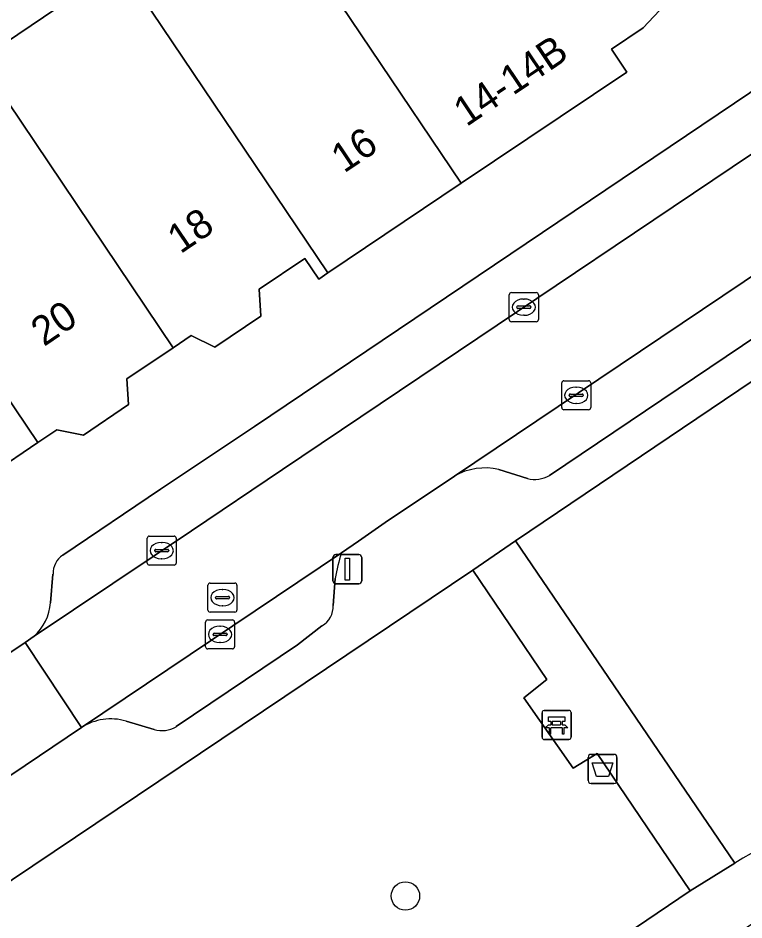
# Model space of a CAD drawing. Extents: x 159960 to 160866, y 382700 to 383354.
# Drawn here: x 160527.58 to 160552.56, y 382938.64 to 382969.69 of the extents above; entities that cross this region are included whole.
import ezdxf

# ---------------------------------------------------------------- set-up
doc = ezdxf.new("R2010")
doc.units = 0
for name, color, linetype in [('IMGEO_Afvalbak', 7, 'Continuous'), ('IMGEO_Bank', 7, 'Continuous'), ('IMGEO_Boom', 7, 'Continuous'), ('IMGEO_Erf', 7, 'Continuous'), ('IMGEO_Groenvoorziening', 7, 'Continuous'), ('IMGEO_Kolk', 7, 'Continuous'), ('IMGEO_Lichtmast', 7, 'Continuous'), ('IMGEO_Pand', 7, 'Continuous'), ('IMGEO_Pand_nummerreeks', 7, 'Continuous'), ('IMGEO_Parkeervlak_open', 7, 'Continuous'), ('IMGEO_Rijbaan_lokaal_gesloten', 7, 'Continuous'), ('IMGEO_Rijbaan_lokaal_open', 7, 'Continuous'), ('IMGEO_Rioolput', 7, 'Continuous'), ('IMGEO_Voetpad_open', 7, 'Continuous')]:
    doc.layers.add(name, color=color, linetype=linetype)

msp = doc.modelspace()

# ---------------------------------------------------------------- linework, layer by layer
at = {"layer": 'IMGEO_Afvalbak'}
for p, q in [((160547.296, 382944.34), (160548.086, 382944.34)), ((160548.086, 382944.34), (160547.296, 382944.34)), ((160547.196, 382943.44), (160547.196, 382944.24)), ((160547.196, 382944.24), (160547.196, 382943.44)), ((160548.186, 382944.24), (160548.186, 382943.44)), ((160548.186, 382943.44), (160548.186, 382944.24)), ((160548.086, 382943.34), (160547.296, 382943.34)), ((160547.296, 382943.34), (160548.086, 382943.34))]:
    msp.add_line(p, q, dxfattribs=at)
msp.add_lwpolyline([(160547.339, 382944.054), (160548.043, 382944.054), (160547.894, 382943.584), (160547.488, 382943.584), (160547.339, 382944.054)], dxfattribs=at)
for centre, start, end in [((160547.296, 382944.24), 90, 180), ((160547.296, 382944.24), 90, 180), ((160548.086, 382944.24), 0, 90), ((160548.086, 382944.24), 360, 90), ((160547.296, 382943.44), 180, 270), ((160547.296, 382943.44), 180, 270), ((160548.086, 382943.44), 270, 0), ((160548.086, 382943.44), 270, 0)]:
    msp.add_arc(centre, 0.1, start, end, dxfattribs=at)
at = {"layer": 'IMGEO_Bank'}
for p, q in [((160545.685, 382945.854), (160546.526, 382945.854)), ((160546.526, 382945.854), (160545.685, 382945.854)), ((160545.61, 382944.929), (160545.61, 382945.77)), ((160545.61, 382945.77), (160545.61, 382944.929)), ((160546.61, 382945.779), (160546.61, 382944.938)), ((160546.61, 382944.938), (160546.61, 382945.779)), ((160546.307, 382945.252), (160545.914, 382945.252)), ((160545.919, 382945.36), (160545.919, 382945.466)), ((160545.963, 382945.466), (160545.963, 382945.36)), ((160546.251, 382945.472), (160545.969, 382945.472)), ((160545.969, 382945.354), (160546.251, 382945.354)), ((160546.257, 382945.36), (160546.257, 382945.466)), ((160546.301, 382945.466), (160546.301, 382945.36)), ((160546.535, 382944.854), (160545.694, 382944.854)), ((160545.694, 382944.854), (160546.535, 382944.854))]:
    msp.add_line(p, q, dxfattribs=at)
for points in [[(160545.913, 382945.472), (160545.827, 382945.472), (160545.827, 382945.633), (160546.39, 382945.633), (160546.39, 382945.472), (160546.307, 382945.472)], [(160545.857, 382945.252), (160545.715, 382945.252), (160545.827, 382945.354), (160545.913, 382945.354)], [(160545.907, 382945.245), (160545.907, 382945.038), (160545.864, 382945.038), (160545.864, 382945.245)], [(160546.307, 382945.354), (160546.39, 382945.354), (160546.502, 382945.252), (160546.363, 382945.252)], [(160546.357, 382945.245), (160546.357, 382945.038), (160546.313, 382945.038), (160546.313, 382945.245)]]:
    msp.add_lwpolyline(points, dxfattribs=at)
for centre, radius, start, end in [((160545.688, 382945.776), 0.0779, 92.4484, 184.2845), ((160545.688, 382945.776), 0.0779, 92.4484, 184.2845), ((160546.532, 382945.776), 0.0779, 2.4484, 94.2845), ((160546.532, 382945.776), 0.0779, 2.4484, 94.2845), ((160545.857, 382945.245), 0.00671, 2.8957, 87.1043), ((160545.914, 382945.245), 0.00671, 92.8957, 177.1043), ((160545.912, 382945.465), 0.00671, 2.8957, 87.1043), ((160545.912, 382945.361), 0.00671, 272.8957, 357.1043), ((160545.969, 382945.465), 0.00671, 92.8957, 177.1043), ((160545.969, 382945.361), 0.00671, 182.8957, 267.1043), ((160546.251, 382945.465), 0.00671, 2.8957, 87.1043), ((160546.251, 382945.361), 0.00671, 272.8957, 357.1043), ((160546.308, 382945.465), 0.00671, 92.8957, 177.1043), ((160546.308, 382945.361), 0.00671, 182.8957, 267.1043), ((160546.306, 382945.245), 0.00671, 2.8957, 87.1043), ((160546.363, 382945.245), 0.00671, 92.8957, 177.1043), ((160545.688, 382944.932), 0.0779, 182.4484, 274.2845), ((160545.688, 382944.932), 0.0779, 182.4484, 274.2845), ((160546.532, 382944.932), 0.0779, 272.4484, 4.2845), ((160546.532, 382944.932), 0.0779, 272.4484, 4.2845)]:
    msp.add_arc(centre, radius, start, end, dxfattribs=at)
at = {"layer": 'IMGEO_Boom'}
msp.add_circle((160540.911, 382939.468), 0.489, dxfattribs=at)
at = {"layer": 'IMGEO_Erf'}
msp.add_lwpolyline([(160502.775, 382952.364), (160507.464, 382955.534), (160512.198, 382958.735), (160516.845, 382961.877), (160521.541, 382965.052), (160526.252, 382968.237), (160531.102, 382971.516)], dxfattribs=at)
at = {"layer": 'IMGEO_Groenvoorziening'}
for points in [[(160564.76, 382965.194), (160563.415, 382964.323), (160544.698, 382951.695), (160552.24, 382940.596)], [(160543.966, 382935.075), (160550.712, 382939.643), (160547.503, 382944.374), (160546.683, 382943.866), (160544.984, 382946.283), (160545.775, 382946.922), (160543.226, 382950.68), (160500, 382921.626), (160496.721, 382919.422), (160500, 382914.514), (160503.626, 382909.085), (160504.654, 382907.546), (160527.954, 382923.207)]]:
    msp.add_lwpolyline(points, dxfattribs=at)
msp.add_arc((160569.366, 382912.423), 32.97, 103.0217, 121.2945, dxfattribs=at)
at = {"layer": 'IMGEO_Kolk'}
for p, q in [((160544.483, 382959.31), (160544.483, 382960.162)), ((160544.558, 382960.236), (160545.41, 382960.236)), ((160545.484, 382960.162), (160545.484, 382959.31)), ((160544.971, 382960.016), (160544.996, 382960.016)), ((160544.742, 382959.73), (160544.742, 382959.742)), ((160545.18, 382959.693), (160544.782, 382959.693)), ((160544.785, 382959.779), (160545.183, 382959.779)), ((160545.226, 382959.742), (160545.226, 382959.73)), ((160545.41, 382959.236), (160544.558, 382959.236)), ((160544.994, 382959.456), (160544.969, 382959.456)), ((160546.287, 382956.277), (160546.287, 382957.129)), ((160546.362, 382957.203), (160547.214, 382957.203)), ((160547.288, 382957.129), (160547.288, 382956.277)), ((160546.589, 382956.746), (160546.987, 382956.746)), ((160546.775, 382956.983), (160546.8, 382956.983)), ((160546.546, 382956.697), (160546.546, 382956.709)), ((160546.984, 382956.66), (160546.586, 382956.66)), ((160546.798, 382956.423), (160546.773, 382956.423)), ((160547.03, 382956.709), (160547.03, 382956.697)), ((160547.214, 382956.203), (160546.362, 382956.203)), ((160532.024, 382950.929), (160532.024, 382951.781)), ((160532.099, 382951.855), (160532.951, 382951.855)), ((160533.025, 382951.781), (160533.025, 382950.929)), ((160532.512, 382951.635), (160532.537, 382951.635)), ((160532.283, 382951.349), (160532.283, 382951.361)), ((160532.721, 382951.312), (160532.323, 382951.312)), ((160532.326, 382951.398), (160532.724, 382951.398)), ((160532.767, 382951.361), (160532.767, 382951.349)), ((160532.951, 382950.855), (160532.099, 382950.855)), ((160532.535, 382951.075), (160532.51, 382951.075)), ((160534.108, 382948.972), (160534.96, 382948.972)), ((160534.033, 382948.046), (160534.033, 382948.898)), ((160534.521, 382948.752), (160534.546, 382948.752)), ((160535.034, 382948.898), (160535.034, 382948.046)), ((160534.292, 382948.466), (160534.292, 382948.478)), ((160534.73, 382948.429), (160534.332, 382948.429)), ((160534.335, 382948.515), (160534.733, 382948.515)), ((160534.776, 382948.478), (160534.776, 382948.466)), ((160534.544, 382948.192), (160534.519, 382948.192)), ((160534.96, 382947.972), (160534.108, 382947.972))]:
    msp.add_line(p, q, dxfattribs=at)
for points in [[(160544.483, 382959.31), (160544.483, 382960.162)], [(160544.558, 382960.236), (160545.41, 382960.236)], [(160545.484, 382960.162), (160545.484, 382959.31)], [(160545.41, 382959.236), (160544.558, 382959.236)], [(160546.287, 382956.277), (160546.287, 382957.129)], [(160546.362, 382957.203), (160547.214, 382957.203)], [(160547.288, 382957.129), (160547.288, 382956.277)], [(160547.214, 382956.203), (160546.362, 382956.203)], [(160532.024, 382950.929), (160532.024, 382951.781)], [(160532.099, 382951.855), (160532.951, 382951.855)], [(160533.025, 382951.781), (160533.025, 382950.929)], [(160532.951, 382950.855), (160532.099, 382950.855)], [(160534.108, 382948.972), (160534.96, 382948.972)], [(160534.033, 382948.046), (160534.033, 382948.898)], [(160535.034, 382948.898), (160535.034, 382948.046)], [(160534.96, 382947.972), (160534.108, 382947.972)]]:
    msp.add_lwpolyline(points, dxfattribs=at)
for centre, radius, start, end in [((160544.56, 382960.16), 0.0765, 91.552, 178.448), ((160544.56, 382960.16), 0.0765, 91.552, 178.448), ((160545.408, 382960.16), 0.0765, 1.552, 88.448), ((160545.408, 382960.16), 0.0765, 1.552, 88.448), ((160544.782, 382959.739), 0.0403, 85.8775, 175.7526), ((160544.779, 382959.729), 0.0366, 178.938, 274.7102), ((160545.183, 382959.736), 0.043, 264.8664, 352.4533), ((160545.187, 382959.741), 0.0386, 1.7309, 96.639), ((160544.56, 382959.312), 0.0765, 181.552, 268.448), ((160544.56, 382959.312), 0.0765, 181.552, 268.448), ((160545.408, 382959.312), 0.0765, 271.552, 358.448), ((160545.408, 382959.312), 0.0765, 271.552, 358.448), ((160546.364, 382957.127), 0.0765, 91.552, 178.448), ((160546.364, 382957.127), 0.0765, 91.552, 178.448), ((160547.212, 382957.127), 0.0765, 1.552, 88.448), ((160547.212, 382957.127), 0.0765, 1.552, 88.448), ((160546.586, 382956.706), 0.0403, 85.8775, 175.7526), ((160546.991, 382956.708), 0.0386, 1.7309, 96.639), ((160546.583, 382956.696), 0.0366, 178.938, 274.7102), ((160546.987, 382956.703), 0.043, 264.8664, 352.4533), ((160546.364, 382956.279), 0.0765, 181.552, 268.448), ((160546.364, 382956.279), 0.0765, 181.552, 268.448), ((160547.212, 382956.279), 0.0765, 271.552, 358.448), ((160547.212, 382956.279), 0.0765, 271.552, 358.448), ((160532.101, 382951.779), 0.0765, 91.552, 178.448), ((160532.101, 382951.779), 0.0765, 91.552, 178.448), ((160532.949, 382951.779), 0.0765, 1.552, 88.448), ((160532.949, 382951.779), 0.0765, 1.552, 88.448), ((160532.323, 382951.358), 0.0403, 85.8775, 175.7526), ((160532.32, 382951.348), 0.0366, 178.938, 274.7102), ((160532.724, 382951.355), 0.043, 264.8664, 352.4533), ((160532.728, 382951.36), 0.0386, 1.7309, 96.639), ((160532.101, 382950.931), 0.0765, 181.552, 268.448), ((160532.101, 382950.931), 0.0765, 181.552, 268.448), ((160532.949, 382950.931), 0.0765, 271.552, 358.448), ((160532.949, 382950.931), 0.0765, 271.552, 358.448), ((160534.11, 382948.896), 0.0765, 91.552, 178.448), ((160534.11, 382948.896), 0.0765, 91.552, 178.448), ((160534.958, 382948.896), 0.0765, 1.552, 88.448), ((160534.958, 382948.896), 0.0765, 1.552, 88.448), ((160534.332, 382948.475), 0.0403, 85.8775, 175.7526), ((160534.329, 382948.465), 0.0366, 178.938, 274.7102), ((160534.733, 382948.472), 0.043, 264.8664, 352.4533), ((160534.737, 382948.477), 0.0386, 1.7309, 96.639), ((160534.11, 382948.048), 0.0765, 181.552, 268.448), ((160534.11, 382948.048), 0.0765, 181.552, 268.448), ((160534.958, 382948.048), 0.0765, 271.552, 358.448), ((160534.958, 382948.048), 0.0765, 271.552, 358.448)]:
    msp.add_arc(centre, radius, start, end, dxfattribs=at)
for centre, major_axis, ratio, start_param, end_param in [((160544.97, 382959.736), (-0.387, 0.002), 0.722429, 4.712389, 7.853982), ((160544.995, 382959.736), (-0.39, 0.002), 0.717154, 1.570796, 4.712389), ((160546.774, 382956.703), (-0.387, 0.002), 0.722429, 4.712389, 7.853982), ((160546.799, 382956.703), (-0.39, 0.002), 0.717154, 1.570796, 4.712389), ((160532.511, 382951.355), (-0.387, 0.002), 0.722429, 4.712389, 7.853982), ((160532.536, 382951.355), (-0.39, 0.002), 0.717154, 1.570796, 4.712389), ((160534.52, 382948.472), (-0.387, 0.002), 0.722429, 4.712389, 7.853982), ((160534.545, 382948.472), (-0.39, 0.002), 0.717154, 1.570796, 4.712389)]:
    msp.add_ellipse(centre, major_axis=major_axis, ratio=ratio, start_param=start_param, end_param=end_param, dxfattribs=at)
at = {"layer": 'IMGEO_Lichtmast'}
for p, q in [((160538.518, 382951.217), (160539.308, 382951.217)), ((160539.308, 382951.217), (160538.518, 382951.217)), ((160538.418, 382950.317), (160538.418, 382951.117)), ((160538.418, 382951.117), (160538.418, 382950.317)), ((160539.408, 382951.117), (160539.408, 382950.317)), ((160539.408, 382950.317), (160539.408, 382951.117)), ((160539.308, 382950.217), (160538.518, 382950.217)), ((160538.518, 382950.217), (160539.308, 382950.217))]:
    msp.add_line(p, q, dxfattribs=at)
msp.add_lwpolyline([(160538.838, 382951.092), (160538.988, 382951.092), (160538.988, 382950.342), (160538.838, 382950.342), (160538.838, 382951.092)], dxfattribs=at)
for centre, start, end in [((160538.518, 382951.117), 90, 180), ((160538.518, 382951.117), 90, 180), ((160539.308, 382951.117), 0, 90), ((160539.308, 382951.117), 360, 90), ((160538.518, 382950.317), 180, 270), ((160538.518, 382950.317), 180, 270), ((160539.308, 382950.317), 270, 0), ((160539.308, 382950.317), 270, 0)]:
    msp.add_arc(centre, 0.1, start, end, dxfattribs=at)
at = {"layer": 'IMGEO_Pand'}
for points in [[(160542.248, 382976.778), (160539.98, 382978.761), (160536.898, 382976.678), (160538.403, 382974.45), (160536.607, 382973.237), (160542.83, 382964.001), (160548.525, 382967.83), (160547.997, 382968.615), (160549.091, 382969.35), (160549.833, 382970.148)], [(160536.607, 382973.237), (160535.68, 382974.612), (160531.102, 382971.516), (160538.244, 382960.918), (160542.83, 382964.001)], [(160526.252, 382968.237), (160532.921, 382958.341), (160533.536, 382958.755), (160534.353, 382958.354), (160535.941, 382959.422), (160535.878, 382960.35), (160537.452, 382961.408), (160537.926, 382960.704), (160538.244, 382960.918), (160531.102, 382971.516)], [(160526.252, 382968.237), (160521.541, 382965.052), (160528.264, 382955.075), (160528.916, 382955.514), (160529.83, 382955.335), (160531.388, 382956.382), (160531.327, 382957.27), (160532.921, 382958.341)], [(160516.845, 382961.877), (160523.564, 382951.907), (160524.289, 382952.394), (160525.006, 382952.043), (160526.753, 382953.218), (160526.698, 382954.023), (160528.264, 382955.075), (160521.541, 382965.052)]]:
    msp.add_lwpolyline(points, close=True, dxfattribs=at)
at = {"layer": 'IMGEO_Parkeervlak_open'}
for points in [[(160528.138, 382948.406), (160533.549, 382952.042), (160536.679, 382954.15), (160558.21, 382968.628)], [(160554.974, 382968.604), (160535.715, 382955.631), (160532.484, 382953.473), (160529.119, 382951.203)], [(160555.401, 382962.522), (160542.597, 382953.924)], [(160545.868, 382953.947), (160554.155, 382959.529)], [(160544.124, 382954.151), (160545.109, 382953.839)], [(160538.708, 382951.282), (160529.769, 382945.267)], [(160528.785, 382950.548), (160528.702, 382949.556)], [(160538.429, 382949.469), (160538.491, 382950.396)], [(160537.2, 382948.111), (160538.035, 382948.767)], [(160533.023, 382945.296), (160537.2, 382948.111)], [(160531.299, 382945.487), (160532.26, 382945.2)]]:
    msp.add_lwpolyline(points, dxfattribs=at)
for centre, radius, start, end in [((160543.659, 382952.032), 2.169, 77.6097, 119.3013), ((160545.357, 382954.816), 1.008, 255.7469, 300.4499), ((160529.556, 382950.567), 0.771, 124.5158, 181.448), ((160545.811, 382949.073), 7.439, 162.7227, 169.7533), ((160526.944, 382949.705), 1.765, 312.5971, 355.153), ((160537.636, 382949.453), 0.793, 300.209, 1.1841), ((160530.774, 382943.708), 1.855, 73.5538, 122.8113), ((160532.534, 382946.105), 0.946, 253.1862, 301.1563)]:
    msp.add_arc(centre, radius, start, end, dxfattribs=at)
at = {"layer": 'IMGEO_Rijbaan_lokaal_gesloten'}
msp.add_arc((160569.011, 382913.206), 30.019, 101.6999, 123.2365, dxfattribs=at)
at = {"layer": 'IMGEO_Rijbaan_lokaal_open'}
for points in [[(160555.401, 382962.522), (160561.566, 382966.661), (160559.548, 382969.562), (160558.21, 382968.628), (160536.679, 382954.15), (160533.549, 382952.042), (160528.138, 382948.406), (160527.829, 382948.198), (160529.769, 382945.267), (160538.708, 382951.282), (160539.297, 382951.678), (160540.214, 382952.323), (160542.597, 382953.924)], [(160529.769, 382945.267), (160527.829, 382948.198), (160525.372, 382946.547), (160527.336, 382943.63)]]:
    msp.add_lwpolyline(points, close=True, dxfattribs=at)
at = {"layer": 'IMGEO_Rioolput'}
for p, q in [((160534.189, 382950.237), (160535.041, 382950.237)), ((160534.114, 382949.311), (160534.114, 382950.163)), ((160534.602, 382950.017), (160534.627, 382950.017)), ((160535.115, 382950.163), (160535.115, 382949.311)), ((160534.373, 382949.731), (160534.373, 382949.743)), ((160534.811, 382949.694), (160534.413, 382949.694)), ((160534.416, 382949.78), (160534.814, 382949.78)), ((160534.857, 382949.743), (160534.857, 382949.731)), ((160534.625, 382949.457), (160534.6, 382949.457)), ((160535.041, 382949.237), (160534.189, 382949.237))]:
    msp.add_line(p, q, dxfattribs=at)
for points in [[(160534.189, 382950.237), (160535.041, 382950.237)], [(160534.114, 382949.311), (160534.114, 382950.163)], [(160535.115, 382950.163), (160535.115, 382949.311)], [(160535.041, 382949.237), (160534.189, 382949.237)]]:
    msp.add_lwpolyline(points, dxfattribs=at)
for centre, radius, start, end in [((160534.191, 382950.161), 0.0765, 91.552, 178.448), ((160534.191, 382950.161), 0.0765, 91.552, 178.448), ((160535.039, 382950.161), 0.0765, 1.552, 88.448), ((160535.039, 382950.161), 0.0765, 1.552, 88.448), ((160534.413, 382949.74), 0.0403, 85.8775, 175.7526), ((160534.41, 382949.73), 0.0366, 178.938, 274.7102), ((160534.814, 382949.737), 0.043, 264.8664, 352.4533), ((160534.818, 382949.742), 0.0386, 1.7309, 96.639), ((160534.191, 382949.313), 0.0765, 181.552, 268.448), ((160534.191, 382949.313), 0.0765, 181.552, 268.448), ((160535.039, 382949.313), 0.0765, 271.552, 358.448), ((160535.039, 382949.313), 0.0765, 271.552, 358.448)]:
    msp.add_arc(centre, radius, start, end, dxfattribs=at)
for centre, major_axis, ratio, start_param, end_param in [((160534.601, 382949.737), (-0.387, 0.002), 0.722429, 4.712389, 7.853982), ((160534.626, 382949.737), (-0.39, 0.002), 0.717154, 1.570796, 4.712389)]:
    msp.add_ellipse(centre, major_axis=major_axis, ratio=ratio, start_param=start_param, end_param=end_param, dxfattribs=at)
at = {"layer": 'IMGEO_Voetpad_open'}
for points in [[(160549.833, 382970.148), (160549.091, 382969.35), (160547.997, 382968.615), (160548.525, 382967.83), (160542.83, 382964.001), (160538.244, 382960.918), (160537.926, 382960.704), (160537.452, 382961.408), (160535.878, 382960.35), (160535.941, 382959.422), (160534.353, 382958.354), (160533.536, 382958.755), (160532.921, 382958.341), (160531.327, 382957.27), (160531.388, 382956.382), (160529.83, 382955.335), (160528.916, 382955.514), (160528.264, 382955.075), (160526.698, 382954.023)], [(160529.119, 382951.203), (160532.484, 382953.473), (160535.715, 382955.631), (160554.974, 382968.604)], [(160410.07, 382861.949), (160415.268, 382865.398), (160416.783, 382866.403), (160416.621, 382866.647), (160416.118, 382867.403), (160433.527, 382879.124), (160435.03, 382880.147), (160459.475, 382896.568), (160460.477, 382895.074), (160462.489, 382896.421), (160465.846, 382898.668), (160467.857, 382900.011), (160495.193, 382918.403), (160496.721, 382919.422), (160500, 382921.626), (160543.226, 382950.68), (160544.698, 382951.695), (160563.415, 382964.323)], [(160554.155, 382959.529), (160545.868, 382953.947)], [(160545.109, 382953.839), (160544.124, 382954.151)], [(160542.597, 382953.924), (160540.214, 382952.323), (160539.297, 382951.678), (160538.708, 382951.282)], [(160528.702, 382949.556), (160528.785, 382950.548)], [(160538.491, 382950.396), (160538.429, 382949.469)], [(160538.035, 382948.767), (160537.2, 382948.111), (160533.023, 382945.296)], [(160525.122, 382946.379), (160525.372, 382946.547), (160527.829, 382948.198), (160528.138, 382948.406)], [(160529.769, 382945.267), (160527.336, 382943.63), (160527.135, 382943.495)], [(160532.26, 382945.2), (160531.299, 382945.487)], [(160552.24, 382940.596), (160550.712, 382939.643), (160543.966, 382935.075)]]:
    msp.add_lwpolyline(points, dxfattribs=at)
msp.add_lwpolyline([(160544.698, 382951.695), (160543.226, 382950.68), (160545.775, 382946.922), (160544.984, 382946.283), (160546.683, 382943.866), (160547.503, 382944.374), (160550.712, 382939.643), (160552.24, 382940.596)], close=True, dxfattribs=at)
for centre, radius, start, end in [((160543.659, 382952.032), 2.169, 77.6097, 119.3013), ((160545.357, 382954.816), 1.008, 255.7469, 300.4499), ((160529.556, 382950.567), 0.771, 124.5158, 181.448), ((160545.811, 382949.073), 7.439, 162.7227, 169.7533), ((160526.944, 382949.705), 1.765, 312.5971, 355.153), ((160537.636, 382949.453), 0.793, 300.209, 1.1841), ((160530.774, 382943.708), 1.855, 73.5538, 122.8113), ((160532.534, 382946.105), 0.946, 253.1862, 301.1563), ((160569.366, 382912.423), 32.97, 103.0217, 121.2945), ((160569.011, 382913.206), 30.019, 101.6999, 123.2365)]:
    msp.add_arc(centre, radius, start, end, dxfattribs=at)

# ---------------------------------------------------------------- texts
at = {"layer": 'IMGEO_Pand_nummerreeks'}
for s, rotation, p in [('14-14B', 33.9134, (160543.008, 382965.928)), ('16', 33.9076, (160538.797, 382964.329)), ('18', 34.0889, (160533.167, 382961.551)), ('20', 34.2619, (160528.474, 382958.361))]:
    msp.add_text(s, height=1, rotation=rotation, dxfattribs=at).set_placement(p)

doc.saveas('drawing.dxf')
